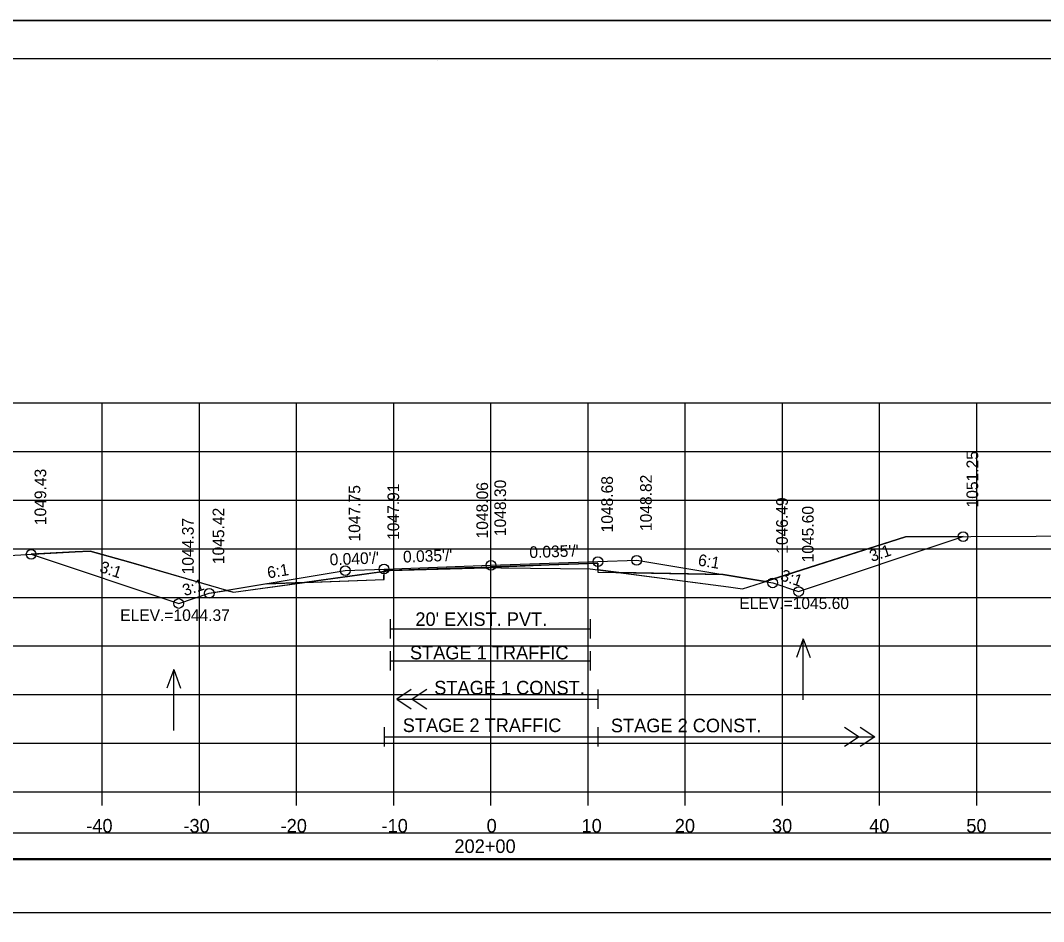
# Model space of a CAD drawing. Extents: x 1370565 to 1374448, y 301010 to 304637.
# Drawn here: x 1373320.4 to 1373425.7, y 301205.6 to 301298.3 of the extents above; entities that cross this region are included whole.
import ezdxf

# ---------------------------------------------------------------- set-up
doc = ezdxf.new("R2010")
doc.units = 0
for name, color, linetype in [('Default', 7, 'Continuous'), ('R_Alt Surface', 7, 'Continuous'), ('R_Axis', 7, 'Continuous'), ('R_Axis Annot', 7, 'Continuous'), ('R_Border', 7, 'Continuous'), ('R_Contours', 7, 'Continuous'), ('R_Drive', 7, 'Continuous'), ('R_Exist Surface', 7, 'Continuous'), ('R_Fin Surface', 7, 'Continuous'), ('R_Grid', 7, 'Continuous'), ('R_No Plot', 7, 'Continuous'), ('R_Water', 7, 'Continuous'), ('R_Water Annot', 7, 'Continuous'), ('R_Xsect Elev', 7, 'Continuous'), ('R_Xsect Slope', 7, 'Continuous')]:
    doc.layers.add(name, color=color, linetype=linetype)

msp = doc.modelspace()

# ---------------------------------------------------------------- linework, layer by layer
at = {"layer": 'Default'}
msp.add_lwpolyline([(1373219.61, 301212), (1373518.02, 301212), (1373518.02, 301214.71), (1373219.61, 301214.71)], close=True, dxfattribs=at)
at = {"layer": 'R_Alt Surface'}
for points in [[(1373345.74, 301240.37), (1373357.81, 301240.79), (1373357.8, 301240.79), (1373357.81, 301241.71), (1373368.81, 301242.09), (1373379.81, 301242.48), (1373379.82, 301241.56), (1373379.81, 301241.56), (1373392.7, 301241.3)], [(1373360.61, 301229.49), (1373359.11, 301228.49), (1373360.61, 301227.49)], [(1373362.21, 301229.49), (1373360.71, 301228.49), (1373362.21, 301227.49)], [(1373359.11, 301228.49), (1373379.81, 301228.49)], [(1373357.81, 301225.62), (1373357.81, 301223.62)], [(1373379.81, 301225.62), (1373379.81, 301223.62)], [(1373379.81, 301225.62), (1373379.81, 301223.62)], [(1373405.21, 301225.62), (1373406.71, 301224.62), (1373405.21, 301223.62)], [(1373406.8, 301225.62), (1373408.3, 301224.62), (1373406.8, 301223.62)], [(1373357.81, 301224.62), (1373379.81, 301224.62)], [(1373379.81, 301224.62), (1373408.3, 301224.62)]]:
    msp.add_lwpolyline(points, dxfattribs=at)
at = {"layer": 'R_Axis'}
for p, q in [((1373218.81, 301218.96), (1373518.81, 301218.96)), ((1373328.81, 301217.56), (1373328.81, 301218.96)), ((1373338.81, 301217.56), (1373338.81, 301218.96)), ((1373348.81, 301217.56), (1373348.81, 301218.96)), ((1373358.81, 301217.56), (1373358.81, 301218.96)), ((1373368.81, 301217.56), (1373368.81, 301218.96)), ((1373378.81, 301217.56), (1373378.81, 301218.96)), ((1373388.81, 301217.56), (1373388.81, 301218.96)), ((1373398.81, 301217.56), (1373398.81, 301218.96)), ((1373408.81, 301217.56), (1373408.81, 301218.96)), ((1373418.81, 301217.56), (1373418.81, 301218.96))]:
    msp.add_line(p, q, dxfattribs=at)
for points in [[(1373358.44, 301236.72), (1373358.44, 301234.72)], [(1373379.02, 301236.72), (1373379.02, 301234.72)], [(1373358.44, 301235.72), (1373379.02, 301235.72)], [(1373358.44, 301233.43), (1373358.44, 301231.43)], [(1373379.02, 301233.43), (1373379.02, 301231.43)], [(1373358.44, 301232.43), (1373379.02, 301232.43)], [(1373379.81, 301229.49), (1373379.81, 301227.49)]]:
    msp.add_lwpolyline(points, dxfattribs=at)
at = {"layer": 'R_Border'}
for p, q in [((1373210.81, 301294.42), (1373526.99, 301294.42)), ((1373363.33, 301294.16), (1373363.33, 301294.16)), ((1373363.33, 301294.16), (1373363.33, 301294.16))]:
    msp.add_line(p, q, dxfattribs=at)
at = {"layer": 'R_Contours'}
for p, q in [((1373341.63, 301239.68), (1373331.51, 301242.6)), ((1373379.81, 301242.48), (1373368.81, 301242.09)), ((1373379.81, 301242.48), (1373369.81, 301242.06)), ((1373379.82, 301241.8), (1373379.81, 301242.48)), ((1373379.82, 301241.8), (1373379.81, 301242.48)), ((1373358.44, 301241.72), (1373357.81, 301241.71)), ((1373357.81, 301240.79), (1373357.81, 301241.63)), ((1373357.82, 301241.63), (1373358.44, 301241.72)), ((1373367.07, 301242.03), (1373358.44, 301241.73)), ((1373358.44, 301241.72), (1373367.07, 301241.98)), ((1373358.44, 301241.72), (1373361.84, 301241.82)), ((1373361.84, 301241.82), (1373358.44, 301241.72)), ((1373368.43, 301242.02), (1373367.07, 301241.98)), ((1373367.07, 301241.97), (1373368.43, 301242.01)), ((1373368.81, 301242.02), (1373368.43, 301242.02)), ((1373368.43, 301242.01), (1373368.81, 301242.02)), ((1373381.97, 301241.52), (1373379.82, 301241.8)), ((1373379.82, 301241.8), (1373379.82, 301241.56)), ((1373379.82, 301241.56), (1373381.97, 301241.52)), ((1373392.7, 301241.3), (1373381.97, 301241.52)), ((1373397.03, 301240.58), (1373392.7, 301241.3)), ((1373345.74, 301240.37), (1373341.63, 301239.68)), ((1373349.63, 301240.5), (1373345.74, 301240.37)), ((1373349.63, 301240.5), (1373357.81, 301240.79)), ((1373397.03, 301240.58), (1373397.81, 301240.45))]:
    msp.add_line(p, q, dxfattribs=at)
for points in [[(1373417.4, 301245.21), (1373411.48, 301245.18), (1373397.03, 301240.58)], [(1373397.81, 301240.45), (1373400.47, 301239.56), (1373417.4, 301245.21)], [(1373331.51, 301242.6), (1373327.57, 301243.72), (1373326.01, 301243.64), (1373321.49, 301243.39)], [(1373321.49, 301243.39), (1373336.67, 301238.33), (1373339.81, 301239.38), (1373341.63, 301239.68)], [(1373357.81, 301241.63), (1373355.28, 301241.29), (1373349.63, 301240.5)], [(1373357.81, 301241.71), (1373357.82, 301241.63)], [(1373358.44, 301241.73), (1373358.44, 301241.72)], [(1373358.44, 301241.72), (1373358.44, 301241.72)], [(1373358.44, 301241.72), (1373358.44, 301241.72)], [(1373367.07, 301241.98), (1373367.07, 301242.03)], [(1373367.07, 301241.98), (1373367.07, 301241.97)], [(1373368.43, 301242.01), (1373368.43, 301242.02)], [(1373368.43, 301242.02), (1373368.43, 301242.01)], [(1373368.81, 301242.09), (1373368.81, 301242.02)], [(1373368.81, 301242.02), (1373369.81, 301242.01), (1373379.02, 301241.91), (1373379.82, 301241.8)], [(1373369.81, 301242.06), (1373369.81, 301242.01)], [(1373369.81, 301242.01), (1373379.02, 301241.91), (1373379.82, 301241.8)], [(1373381.97, 301241.52), (1373393.25, 301240.03), (1373394.68, 301239.84), (1373396.64, 301240.46), (1373397.03, 301240.58)], [(1373341.63, 301239.68), (1373342.31, 301239.49), (1373349.63, 301240.5)]]:
    msp.add_lwpolyline(points, dxfattribs=at)
at = {"layer": 'R_Drive'}
msp.add_lwpolyline([(1373219.61, 301206.53), (1373518.02, 301206.53), (1373518.02, 301212.05), (1373219.61, 301212.05)], close=True, dxfattribs=at)
at = {"layer": 'R_Exist Surface'}
msp.add_lwpolyline([(1373295.5, 301241.96), (1373326.01, 301243.64), (1373327.57, 301243.72), (1373331.51, 301242.6), (1373342.31, 301239.49), (1373355.28, 301241.29), (1373358.44, 301241.72), (1373367.07, 301241.98), (1373368.43, 301242.02), (1373369.81, 301242.01), (1373379.02, 301241.91), (1373393.25, 301240.03), (1373394.68, 301239.84), (1373396.64, 301240.46), (1373411.48, 301245.18), (1373445.11, 301245.35)], dxfattribs=at)
at = {"layer": 'R_Fin Surface'}
msp.add_lwpolyline([(1373321.49, 301243.39), (1373336.67, 301238.33), (1373339.81, 301239.38), (1373353.81, 301241.71), (1373357.81, 301241.87), (1373368.81, 301242.26), (1373379.81, 301242.64), (1373383.81, 301242.78), (1373397.81, 301240.45), (1373400.47, 301239.56), (1373417.4, 301245.21)], dxfattribs=at)
at = {"layer": 'R_Grid'}
for p, q in [((1373218.81, 301258.96), (1373518.81, 301258.96)), ((1373328.81, 301218.96), (1373328.81, 301258.96)), ((1373338.81, 301218.96), (1373338.81, 301258.96)), ((1373348.81, 301218.96), (1373348.81, 301258.96)), ((1373358.81, 301218.96), (1373358.81, 301258.96)), ((1373368.81, 301218.96), (1373368.81, 301258.96)), ((1373378.81, 301218.96), (1373378.81, 301258.96)), ((1373388.81, 301218.96), (1373388.81, 301258.96)), ((1373398.81, 301218.96), (1373398.81, 301258.96)), ((1373408.81, 301218.96), (1373408.81, 301258.96)), ((1373418.81, 301218.96), (1373418.81, 301258.96)), ((1373218.81, 301253.96), (1373518.81, 301253.96)), ((1373218.81, 301248.96), (1373518.81, 301248.96)), ((1373218.81, 301243.96), (1373518.81, 301243.96)), ((1373218.81, 301238.96), (1373518.81, 301238.96)), ((1373218.81, 301233.96), (1373518.81, 301233.96)), ((1373218.81, 301228.96), (1373518.81, 301228.96)), ((1373218.81, 301223.96), (1373518.81, 301223.96)), ((1373218.81, 301218.96), (1373518.81, 301218.96))]:
    msp.add_line(p, q, dxfattribs=at)
at = {"layer": 'R_No Plot'}
msp.add_line((1373198.41, 301298.32), (1373531.75, 301298.32), dxfattribs=at)
for points in [[(1373198.41, 301511.65), (1373531.75, 301511.65), (1373531.75, 301298.32), (1373198.41, 301298.32)], [(1373198.41, 301298.32), (1373531.75, 301298.32), (1373531.75, 301084.98), (1373198.41, 301084.98)], [(1373444.73, 301294.42), (1373464.35, 301294.42), (1373464.35, 301284.54), (1373480.47, 301284.54), (1373503.67, 301284.54), (1373503.67, 301251.87), (1373526.87, 301251.87), (1373526.99, 301088.96), (1373210.81, 301088.96), (1373210.81, 301294.42)]]:
    msp.add_lwpolyline(points, close=True, dxfattribs=at)
for centre in [(1373417.4, 301245.21), (1373321.49, 301243.39), (1373357.81, 301241.87), (1373368.81, 301242.26), (1373379.81, 301242.64), (1373383.81, 301242.78), (1373353.81, 301241.71), (1373397.81, 301240.45), (1373339.81, 301239.38), (1373400.47, 301239.56), (1373336.67, 301238.33)]:
    msp.add_circle(centre, 0.5, dxfattribs=at)
at = {"layer": 'R_Water Annot'}
for p, q in [((1373400.95, 301234.71), (1373400.25, 301232.78)), ((1373400.95, 301228.42), (1373400.95, 301234.71)), ((1373400.95, 301234.71), (1373401.65, 301232.78)), ((1373336.16, 301231.55), (1373335.46, 301229.63)), ((1373336.16, 301225.27), (1373336.16, 301231.55)), ((1373336.16, 301231.55), (1373336.86, 301229.63))]:
    msp.add_line(p, q, dxfattribs=at)
at = {"layer": 'R_Xsect Elev'}
msp.add_line((1373368.81, 301242.02), (1373368.81, 301252.02), dxfattribs=at)

# ---------------------------------------------------------------- texts
at = {"layer": 'R_Axis Annot'}
for s, p in [("20' EXIST. PVT.", (1373361.03, 301236.02)), ('-40', (1373327.16, 301214.76)), ('-30', (1373337.16, 301214.76)), ('-20', (1373347.16, 301214.76)), ('-10', (1373357.55, 301214.76)), ('0', (1373368.36, 301214.76)), ('10', (1373378.13, 301214.76)), ('20', (1373387.73, 301214.76)), ('30', (1373397.73, 301214.76)), ('40', (1373407.73, 301214.76)), ('50', (1373417.73, 301214.76)), ('202+00', (1373365.05, 301212.66))]:
    msp.add_text(s, height=1.4, dxfattribs=at).set_placement(p)
at = {"layer": 'R_Water'}
for s, p in [('STAGE 1 TRAFFIC', (1373360.47, 301232.58)), ('STAGE 1 CONST.', (1373362.97, 301228.97)), ('STAGE 2 TRAFFIC', (1373359.73, 301225.1)), ('STAGE 2 CONST.', (1373381.15, 301225.08))]:
    msp.add_text(s, height=1.4, dxfattribs=at).set_placement(p)
at = {"layer": 'R_Xsect Elev'}
for s, p in [('1051.25', (1373418.95, 301248.21)), ('1049.43', (1373323.04, 301246.39)), ('1048.06', (1373368.51, 301245.02)), ('1048.30', (1373370.36, 301245.26)), ('1048.68', (1373381.36, 301245.64)), ('1048.82', (1373385.36, 301245.78)), ('1047.75', (1373355.36, 301244.71)), ('1047.91', (1373359.36, 301244.87)), ('1046.49', (1373399.36, 301243.45)), ('1045.42', (1373341.36, 301242.38)), ('1045.60', (1373402.02, 301242.56)), ('1044.37', (1373338.22, 301241.33))]:
    msp.add_text(s, height=1.2, rotation=90, dxfattribs=at).set_placement(p)
for s, p in [('ELEV.=1045.60', (1373394.37, 301237.76)), ('ELEV.=1044.37', (1373330.65, 301236.53))]:
    msp.add_text(s, height=1.2, dxfattribs=at).set_placement(p)
at = {"layer": 'R_Xsect Slope'}
for s, rotation, p in [("0.035'/'", 2.0045, (1373372.78, 301243)), ("0.040'/'", 2.2906, (1373352.23, 301242.25)), ("0.035'/'", 2.0045, (1373359.78, 301242.54)), ('6:1', 350.5358, (1373390.05, 301242.25)), ('3:1', 18.4332, (1373407.99, 301242.6)), ('3:1', 341.5668, (1373328.45, 301241.6)), ('6:1', 9.4642, (1373345.88, 301240.9)), ('3:1', 341.5651, (1373398.51, 301240.74)), ('3:1', 18.4349, (1373337.29, 301239.07))]:
    msp.add_text(s, height=1.2, rotation=rotation, dxfattribs=at).set_placement(p)

doc.saveas('drawing.dxf')
